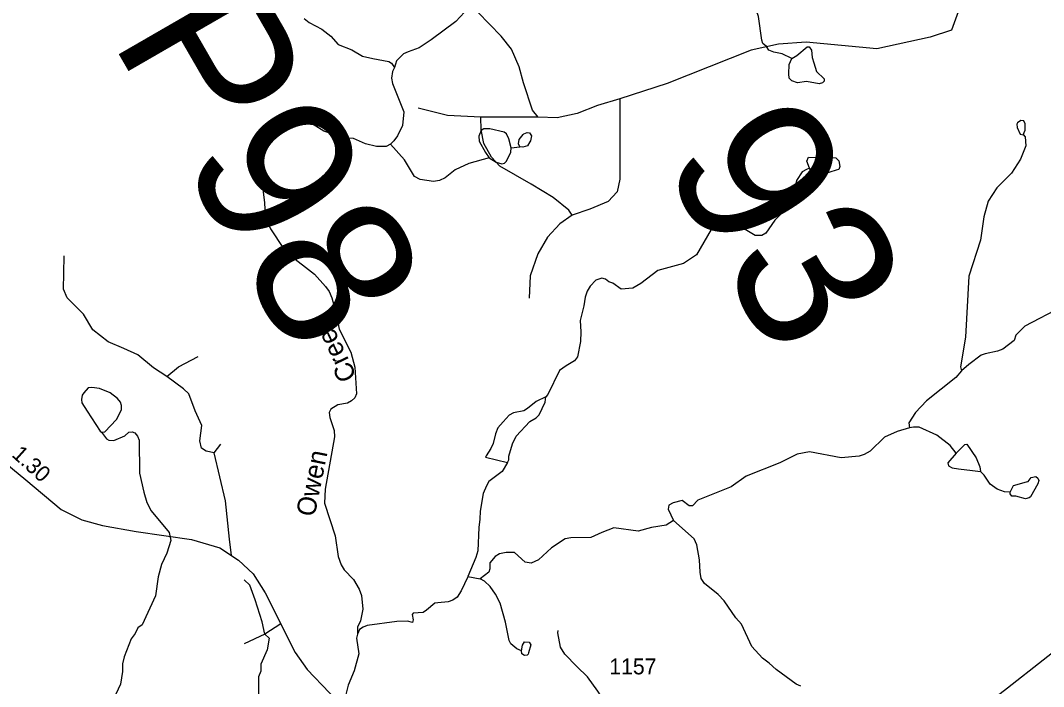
# Model space of a CAD drawing. Extents: x 2056842 to 2160602, y 826753 to 1016856.
# Drawn here: x 2095813 to 2103871, y 917299 to 922545 of the extents above; entities that cross this region are included whole.
import ezdxf

# ---------------------------------------------------------------- set-up
doc = ezdxf.new("R2010")
doc.units = 0
for name, color, linetype in [('Exist Hydrographic Creek Single Shore', 7, 'Continuous'), ('Exist Hydrographic Creek Single Shore Label', 7, 'Continuous'), ('Exist Hydrographic Misc Water Feature', 7, 'Continuous'), ('Exist Hydrographic Pond Under 1500 Sq Ft', 7, 'Continuous'), ('Exist Railroad Mainline', 7, 'Continuous'), ('Exist Road Non-System Type 51', 7, 'Continuous'), ('Exist Road Secondary Mileage Hundredths English Label', 7, 'Continuous'), ('Exist Road Secondary Structure Pipe Number Label', 7, 'Continuous'), ('Exist Road Secondary Structure Standard Bridge Number Label', 7, 'Continuous'), ('Exist Road Secondary Type 51 Attributed', 7, 'Continuous'), ('Exist Road Secondary Type 51 Number Label', 7, 'Continuous')]:
    doc.layers.add(name, color=color, linetype=linetype)

msp = doc.modelspace()

# ---------------------------------------------------------------- linework, layer by layer
at = {"layer": 'Exist Hydrographic Creek Single Shore'}
for points in [[(2099404.7, 922694), (2099308.8, 922609.7), (2099243, 922537.6), (2099047.7, 922393), (2098953.9, 922330.6), (2098865.9, 922298.3), (2098829.8, 922282), (2098774.2, 922228.1), (2098758.4, 922175.9)], [(2098758.4, 922175.9), (2098742.3, 922144.1), (2098734.6, 922092.1), (2098742.6, 922047.9), (2098831.2, 921826.2), (2098821.7, 921718.2), (2098782, 921637.9), (2098753.9, 921598.2), (2098726.1, 921569.9)], [(2098726.1, 921569.9), (2098692.3, 921553.8), (2098616.2, 921553.4), (2098530.3, 921573.3), (2098436, 921616.9), (2098372.1, 921618.9), (2098202, 921674.2), (2098083.7, 921745.9), (2097947.5, 921745.5), (2097901.6, 921731.3), (2097819.8, 921679.2), (2097766.1, 921606.8), (2097724.5, 921494.8), (2097709.1, 921338.6), (2097721.3, 921214.7), (2097735.5, 921111), (2097740.2, 921003), (2097782.4, 920903), (2097884.9, 920749.3), (2097928.8, 920701.4), (2098127.4, 920546.1), (2098215.6, 920450.4), (2098243.7, 920410.4), (2098265.9, 920360.8), (2098300.4, 920236.7), (2098322.8, 920112.8), (2098415.2, 919933.1), (2098447.5, 919813.3), (2098458.3, 919605.4), (2098446.5, 919573.1), (2098420.4, 919549.1), (2098388.5, 919531), (2098312.7, 919516.8), (2098258.6, 919484.5), (2098244.9, 919456.6), (2098249, 919416.8), (2098283.3, 919316.6), (2098285.5, 919264.7), (2098212.7, 918852.5), (2098207.1, 918742.7), (2098292, 918485), (2098316.2, 918323.1), (2098338.5, 918257), (2098362.6, 918217.1), (2098436.8, 918141.4), (2098479.2, 918065.4), (2098499.1, 918015.4), (2098509.7, 917907.6), (2098492, 917815.4), (2098468.1, 917767.4), (2098466.3, 917711.6)], [(2098466.3, 917711.6), (2098458.4, 917679.3), (2098478.8, 917557.5), (2098441.3, 917423.4), (2098393.6, 917309.2), (2098370, 917214.3)]]:
    msp.add_lwpolyline(points, dxfattribs=at)
at = {"layer": 'Exist Hydrographic Misc Water Feature'}
for p, q in [((2099678.4, 921541.1), (2099746.3, 921549.3)), ((2099336.8, 918164.4), (2099432.7, 918148.6))]:
    msp.add_line(p, q, dxfattribs=at)
for points in [[(2101887.8, 922245.9), (2101811.7, 922283.7), (2101745.7, 922295.5), (2101707.6, 922311.4), (2101687.5, 922339.3), (2101659.6, 922363.2), (2101651.4, 922391.2), (2101624.7, 922577.1), (2101608.7, 922621.1), (2101562.2, 922720.8), (2101454.1, 922862.5), (2101409.8, 922928.4), (2101357.3, 923056.2), (2101317.4, 923092.1)], [(2098047.4, 922561.9), (2098087.4, 922530), (2098187.7, 922476.3), (2098257.8, 922420.5), (2098313.8, 922354.7), (2098422, 922315), (2098506.1, 922265.3), (2098588.3, 922245.5), (2098714.2, 922222.1), (2098734.3, 922210.1), (2098758.3, 922176.1)], [(2101887.8, 922245.9), (2101927.8, 922270), (2102007.6, 922336.3), (2102023.6, 922336.4), (2102043.5, 922312.5), (2102047.8, 922252.4), (2102060.1, 922210.5)], [(2102004.3, 922064.3), (2101932.5, 922054.1), (2101888.2, 922069.9), (2101868.3, 922091.8), (2101864.2, 922125.9), (2101866.1, 922197.9), (2101887.8, 922245.9)], [(2102060.1, 922210.5), (2102082, 922144.5), (2102142.3, 922086.7), (2102142.3, 922066.7), (2102130.4, 922054.7), (2102102.5, 922046.6), (2102004.3, 922064.3)], [(2099509.8, 921692.5), (2099461.8, 921692.4), (2099441.7, 921678.4), (2099422.1, 921634.3), (2099426, 921594.3), (2099474.4, 921504.5), (2099504.5, 921464.5)], [(2099678.4, 921541.1), (2099658.1, 921613), (2099640, 921652.9), (2099621.8, 921664.9), (2099509.8, 921692.5)], [(2103709.5, 921645.8), (2103725.5, 921629.8), (2103731.8, 921557.8), (2103688, 921453.6), (2103618.5, 921341.5), (2103502.8, 921227.1), (2103433.3, 921122.9), (2103401.5, 920998.8), (2103374, 920814.8), (2103283, 920530.5), (2103256.5, 920050.4), (2103215.3, 919818.3), (2103223.3, 919786.3)], [(2099504.5, 921464.5), (2099344.8, 921418), (2099236.9, 921369.7), (2099159, 921305.5), (2099113.1, 921285.3), (2099065.1, 921277.2), (2098961.1, 921292.9), (2098917, 921316.6), (2098836.6, 921446.4), (2098726.3, 921570.1)], [(2099504.5, 921464.5), (2099560.5, 921428.7), (2099604.8, 921416.8), (2099624.7, 921420.9), (2099640.6, 921436.9), (2099674.3, 921509.1), (2099678.4, 921541.1)], [(2102028.5, 921382.5), (2102006.3, 921436.4), (2102018.2, 921468.4), (2102198.3, 921466.9)], [(2102198.3, 921466.9), (2102234.4, 921463.2), (2102258.3, 921439.2), (2102266.5, 921395.2), (2102258.5, 921371.2), (2102238.5, 921365.1)], [(2102028.5, 921382.5), (2102002.6, 921372.3), (2101970.5, 921352.3), (2101924.7, 921284.1), (2101889.3, 921132), (2101849.5, 921067.9), (2101753.7, 920971.6), (2101682.1, 920869.4), (2101652.2, 920851.4), (2101600.3, 920851.2), (2101520, 920899), (2101484.1, 920922.7), (2101392, 920952.6), (2101348.1, 920952.4), (2101312, 920944.3), (2101280, 920928.2), (2101252.2, 920900.1), (2101136.7, 920699.7), (2101035, 920631.4), (2100833, 920576.8), (2100699.5, 920472.4), (2100635.6, 920436.3), (2100543.5, 920427.8), (2100479.5, 920475.7), (2100447.5, 920487.6), (2100419.6, 920507.5), (2100391.3, 920515.4), (2100343.6, 920499.3), (2100299.5, 920453.2), (2100275.9, 920413.1), (2100259.9, 920367), (2100250.1, 920297), (2100220.5, 920180.9), (2100226.9, 920093), (2100223, 920016.9), (2100199.4, 919896.9), (2100175.6, 919864.8), (2100109.6, 919824.6), (2100057.7, 919788.4), (2099966.3, 919600.2), (2099950.3, 919580.2)], [(2102238.5, 921365.1), (2102086.7, 921318.7), (2102054.5, 921338.6), (2102028.5, 921382.5)], [(2104075.4, 920304.9), (2104015.7, 920288.8), (2103724.1, 920137.6), (2103652.4, 920067.6), (2103638.4, 920025.6), (2103548.8, 919957.2), (2103506.8, 919941), (2103410.8, 919920.7), (2103378.8, 919908.6), (2103283.1, 919834.4), (2103223.3, 919786.1)], [(2103223.3, 919786.1), (2103179.3, 919734.2), (2102948, 919549.3), (2102862.1, 919457), (2102810.6, 919377), (2102814.7, 919336.9)], [(2096518.7, 919611.3), (2096436.5, 919647.1), (2096374.6, 919654.9), (2096346.5, 919650.8), (2096310.8, 919612.7), (2096298.7, 919592.7), (2096292.8, 919560.7), (2096296.9, 919532.6), (2096339.1, 919468.7)], [(2096451.7, 919303.1), (2096477.5, 919305.2), (2096569.4, 919401.5), (2096609.2, 919477.6), (2096609, 919513.6), (2096601, 919537.6), (2096576.8, 919567.6), (2096518.7, 919611.3)], [(2099950.3, 919580.2), (2099874.6, 919543.9), (2099806.7, 919487.7), (2099776.8, 919471.6), (2099694.8, 919455.3), (2099662.8, 919435.3), (2099615, 919385.1)], [(2099648, 919063.2), (2099658.1, 919085.3), (2099659.7, 919113.3), (2099687.6, 919211.3), (2099717.3, 919271.5), (2099825, 919387.7), (2099874.8, 919415.9), (2099898.8, 919438), (2099946.6, 919540.1), (2099950.3, 919580.2)], [(2096339.1, 919468.7), (2096439.6, 919309.1), (2096451.7, 919303.1)], [(2099615, 919385.1), (2099573.4, 919337), (2099553.3, 919288.9), (2099535.7, 919212.9), (2099517.8, 919172.8), (2099479.9, 919116.6), (2099475.8, 919104.6), (2099648, 919063.2)], [(2096451.7, 919303.1), (2096489.8, 919251.3), (2096507.9, 919239.4), (2096547.8, 919237.4), (2096635.6, 919273.7), (2096665.5, 919301.8), (2096693.6, 919305.9), (2096713.5, 919297.9), (2096733.6, 919270), (2096747.8, 919240.1), (2096750.6, 918980.2), (2096785.1, 918830.3), (2096809.3, 918748.4), (2096843.5, 918682.4), (2096984, 918512.9), (2096998.1, 918449), (2096966.6, 918348.9), (2096922.9, 918260.7), (2096897.3, 918162.6), (2096875.5, 918014.6), (2096770.3, 917786.3), (2096738.5, 917762.2), (2096716.6, 917716.1), (2096684.6, 917674.1), (2096629.3, 917531.9), (2096617.4, 917477.8), (2096617.6, 917417.9), (2096599.9, 917317.8), (2096564, 917237.6)], [(2102814.7, 919336.9), (2102718.9, 919306.7), (2102618.9, 919262.5), (2102505.4, 919153.9), (2102457.3, 919125.7), (2102419.3, 919113.7), (2102277.6, 919101.2), (2102027.2, 919146.5), (2101931.4, 919130.1), (2101793.8, 919061.7), (2101528.1, 918955), (2101410.2, 918872.5), (2101148.5, 918765.7), (2101104.6, 918723.6), (2101080.6, 918721.5), (2101024.7, 918763.3), (2100952.9, 918747.1), (2100920.6, 918727.1), (2100914.8, 918697), (2100957.2, 918607.2)], [(2103181.3, 919136.3), (2103135.4, 919198.1), (2103029.1, 919277.8), (2102890.7, 919341.4), (2102846.8, 919343.2), (2102814.9, 919337.2)], [(2103181.3, 919136.3), (2103117.5, 919062.1), (2103121.8, 919038.1), (2103151.8, 919022.2), (2103199.7, 919014.3)], [(2103181.3, 919136.3), (2103251.2, 919206.6), (2103267.2, 919208.5), (2103339.6, 919100.7), (2103369.7, 919028.9), (2103373.8, 918992.9)], [(2099648, 919063.2), (2099606.4, 918993.1), (2099502.6, 918912.8), (2099482.6, 918880.7), (2099456.9, 918820.6), (2099433.3, 918680.5), (2099431.5, 918616.6), (2099421.7, 918552.5), (2099414.3, 918368.5), (2099400.3, 918314.5), (2099336.8, 918164.4)], [(2103199.7, 919014.3), (2103309.9, 919000.7), (2103373.8, 918992.9)], [(2103608.2, 918829.7), (2103564.3, 918833.6), (2103506.3, 918853.4), (2103450.1, 918893.1), (2103402.1, 918965), (2103373.8, 918992.9)], [(2103608.2, 918829.7), (2103634, 918881.8), (2103736, 918910.1)], [(2103736, 918910.1), (2103750.1, 918914.2), (2103774.1, 918944.2), (2103809.8, 918952.3), (2103826, 918940.4), (2103834, 918922.4), (2103826, 918896.3), (2103768.6, 918792.1), (2103758.5, 918786.2)], [(2103758.5, 918786.2), (2103728.6, 918778), (2103652.3, 918797.8), (2103620.3, 918797.7), (2103608.2, 918817.7), (2103608.2, 918829.7)], [(2100957.3, 918607.4), (2100897.6, 918571.2), (2100781.6, 918550.8), (2100677.6, 918522.5), (2100485.7, 918547.8), (2100391.8, 918511.6), (2100303.8, 918473.3), (2100147.7, 918470.8), (2100101.8, 918462.6), (2099996, 918392.4), (2099892.2, 918296), (2099834.6, 918271.8), (2099786.6, 918279.7), (2099704.4, 918355.5), (2099638.4, 918355.2), (2099586.3, 918343.1), (2099550.4, 918323), (2099508.6, 918272.9), (2099508.6, 918226.8), (2099500.8, 918200.9), (2099432.7, 918148.6)], [(2101959.4, 917302.6), (2101923.3, 917318.5), (2101764.8, 917434), (2101710.9, 917483.9), (2101656.5, 917521.6), (2101572.2, 917615.4), (2101491.9, 917789.1), (2101447.6, 917839), (2101355.3, 917974.7), (2101309.2, 918022.6), (2101200.9, 918110.1), (2101174.8, 918150.1), (2101166.6, 918200.1), (2101160.3, 918296), (2101139.8, 918413.9), (2101117.8, 918461.9), (2100957.3, 918607.4)], [(2099336.6, 918164.1), (2099285.1, 918052), (2099251.3, 918003.8), (2099219.3, 917979.8), (2099181.3, 917965.8), (2099099.4, 917959.3), (2099075.4, 917955.2), (2099009.6, 917899.2), (2098983.6, 917881), (2098905.8, 917876.7), (2098897.7, 917866.7), (2098906, 917824.9), (2098900, 917802.7), (2098861.8, 917812.7), (2098777.8, 917812.4), (2098544.1, 917779.6), (2098512.1, 917767.8), (2098484.1, 917747.7), (2098466.3, 917711.6)], [(2099758.6, 917579.7), (2099722.7, 917595.6), (2099674.5, 917635.4), (2099662.4, 917661.4), (2099634.1, 917805.3), (2099591.6, 917955.1), (2099555.3, 918027), (2099511.1, 918086.9), (2099467.2, 918128.7), (2099432.7, 918148.6)]]:
    msp.add_lwpolyline(points, dxfattribs=at)
at = {"layer": 'Exist Hydrographic Pond Under 1500 Sq Ft'}
for points in [[(2103725, 921731.6), (2103715, 921753.5), (2103691.1, 921757.6), (2103665.1, 921739.4), (2103661, 921729.3)], [(2103661, 921729.3), (2103663, 921701.4), (2103685.3, 921649.4), (2103709.5, 921645.7)], [(2103709.5, 921645.7), (2103725.3, 921681.7), (2103725, 921731.6)], [(2099746.1, 921549), (2099734.2, 921573.2), (2099739.8, 921607.2), (2099771.8, 921647.3), (2099777.8, 921653.4)], [(2099777.8, 921653.4), (2099803.6, 921663.3), (2099821.6, 921661.3), (2099837.9, 921637.4), (2099829.8, 921597.5), (2099824.1, 921589.4)], [(2099824.1, 921589.4), (2099806, 921557.3), (2099770, 921547.2), (2099746.1, 921549)], [(2099758.6, 917579.5), (2099766.4, 917623.6), (2099782.4, 917651.5), (2099820.4, 917649.7)], [(2099820.4, 917649.7), (2099832.4, 917627.8), (2099814.7, 917563.6)], [(2099814.7, 917563.6), (2099812.5, 917553.8), (2099802.5, 917545.8), (2099782.8, 917543.6), (2099762.7, 917555.5), (2099758.6, 917579.5)]]:
    msp.add_lwpolyline(points, dxfattribs=at)
at = {"layer": 'Exist Railroad Mainline'}
msp.add_lwpolyline([(2099514.5, 911843.1), (2099985.4, 912770.4), (2100363.3, 913475.7), (2101055.2, 914795.7), (2101387.3, 915392.7), (2101664.1, 915761.6), (2101749.9, 915827.8), (2101825.6, 915916), (2101927.3, 916010.3), (2103587.1, 917289.4), (2104147.7, 917731.1), (2104494.8, 917984.1), (2104969.8, 918353.5), (2105163.1, 918522.1), (2105641.7, 918981.6), (2105813.1, 919194.1), (2106277.3, 919703.5), (2106454.9, 919884), (2107198.1, 920728.3), (2107564.8, 921135.4), (2107819.8, 921480.1), (2108331.2, 922285.8), (2108494.6, 922468.2), (2108751.8, 922670.9)], dxfattribs=at)
at = {"layer": 'Exist Road Non-System Type 51'}
for p, q in [((2099891.2, 921783.6), (2099438.5, 921783.6)), ((2097337.7, 919138.5), (2097389.8, 919208.6)), ((2097863, 917792.5), (2097737.4, 917712.1)), ((2097737.4, 917712.1), (2097573.9, 917636.6))]:
    msp.add_line(p, q, dxfattribs=at)
for points in [[(2103375.8, 923058), (2103279.1, 922838.8), (2103146.2, 922468.5), (2102977.3, 922414.6), (2102557, 922321.1), (2102000.1, 922375), (2101782.7, 922358.9), (2101567.2, 922312.1), (2100906.1, 922049.7), (2100532.5, 921927.4)], [(2099891.2, 921783.6), (2099844.5, 921839.4), (2099774.4, 922053.3), (2099740.3, 922180.9), (2099680.1, 922320.2), (2099599.3, 922422.7), (2099416.1, 922611.4), (2099207.7, 922814.6)], [(2100532.5, 921927.4), (2100357.3, 921874.4), (2100197.5, 921811.5), (2100041.2, 921777.3), (2099891.2, 921783.6)], [(2100532.5, 921927.4), (2100534.3, 921296.5), (2100512.7, 921195.8), (2100440.9, 921120.3), (2100297.2, 921059.2), (2100157.1, 921012.5)], [(2099438.5, 921783.6), (2099175.4, 921797.1), (2098945.4, 921854.6)], [(2100157.1, 921012.5), (2100132.8, 921051.1), (2100007.1, 921151.8), (2099836.4, 921256), (2099589.4, 921397.2), (2099522.9, 921469.1), (2099461.9, 921576.9), (2099440.3, 921684.8), (2099438.5, 921783.6)], [(2100157.1, 921012.5), (2100060.9, 920943.3), (2099963.9, 920837.2), (2099888.5, 920706), (2099827.4, 920533.4), (2099818.4, 920359)], [(2096966.8, 919741.6), (2096861.7, 919809), (2096737.7, 919911.4), (2096626.3, 919961.8), (2096502.4, 920013.9), (2096382.9, 920108.3), (2096309.3, 920232.3), (2096180, 920359.9), (2096151.2, 920430), (2096154.8, 920554.1), (2096158.4, 920692.5)], [(2096966.8, 919741.6), (2097057.5, 919816.2), (2097213.7, 919898.9)], [(2097337.7, 919138.5), (2097276.6, 919152.9), (2097238.9, 919176.2), (2097224.5, 919233.8), (2097242.5, 919356), (2097188.6, 919471), (2097139.2, 919605), (2097097.9, 919642.7), (2096966.8, 919741.6)], [(2097473.9, 918331.8), (2097458.9, 918459.9), (2097428.4, 918761.9), (2097337.7, 919138.5)], [(2097737.4, 917712.1), (2097715.8, 917809.2), (2097660.1, 917981.7), (2097618.8, 918096.8), (2097573.9, 918139.9)], [(2097737.4, 917712.1), (2097771.5, 917679.7), (2097757.1, 917588.1), (2097706.8, 917474.8), (2097705, 917420.9), (2097687.1, 917374.1), (2097688, 917231.2), (2097666.4, 917130.6), (2097639.5, 916869.9), (2097612.5, 916713.5)], [(2100419, 917032.9), (2100420.2, 917127), (2100407.6, 917188.1), (2100360.9, 917263.6), (2100278.3, 917375), (2100193.9, 917455.9), (2100101.4, 917553.9), (2100065.4, 917609.6), (2100043.9, 917721.1), (2100047.5, 917740.9)]]:
    msp.add_lwpolyline(points, dxfattribs=at)
at = {"layer": 'Exist Road Secondary Type 51 Attributed'}
msp.add_lwpolyline([(2095537.6, 919187.4), (2095854.5, 918927.7), (2096132.8, 918694.1), (2096296.2, 918611.5), (2096459.6, 918568.4), (2096723.6, 918519.8), (2097160.8, 918456.1), (2097383.5, 918391.4), (2097530.7, 918294.3), (2097645.7, 918186.5), (2097740.8, 918037.4), (2097975.2, 917567.5), (2098072.1, 917432.7), (2098246.3, 917249.4), (2098353.5, 917135.8)], dxfattribs=at)

# ---------------------------------------------------------------- texts
at = {"layer": 'Exist Hydrographic Creek Single Shore Label'}
for s, rotation, p in [('Creek', 115.51462, (2098464.8, 919740.6)), ('Owen', 78.62617, (2098128.9, 918630))]:
    msp.add_text(s, height=150, rotation=rotation, dxfattribs=at).set_placement(p)
at = {"layer": 'Exist Road Secondary Mileage Hundredths English Label'}
msp.add_text('1.30', height=125, rotation=317.98606, dxfattribs=at).set_placement((2095737.4, 919116.4))
at = {"layer": 'Exist Road Secondary Structure Pipe Number Label'}
msp.add_text('P98', height=1230.31, rotation=300, dxfattribs=at).set_placement((2096519.6, 922396.3))
at = {"layer": 'Exist Road Secondary Structure Standard Bridge Number Label'}
msp.add_text('93', height=1230.31, rotation=300, dxfattribs=at).set_placement((2100854.9, 921434))
at = {"layer": 'Exist Road Secondary Type 51 Number Label'}
msp.add_text('1157', height=125, dxfattribs=at).set_placement((2100450.3, 917394.9))

doc.saveas('drawing.dxf')
